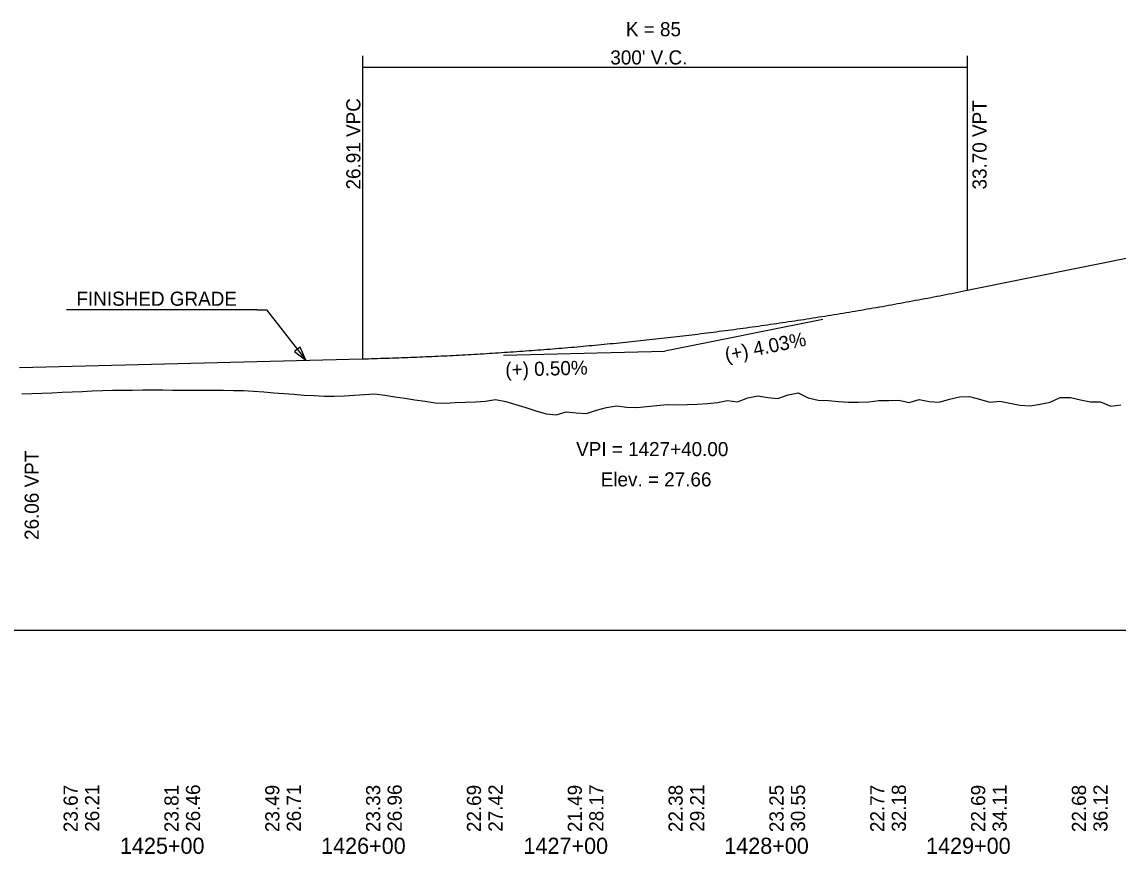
# Model space of a CAD drawing. Extents: x 2360994 to 2383826, y 330623 to 403123.
# Drawn here: x 2370747 to 2371290, y 366762 to 367174 of the extents above; entities that cross this region are included whole.
import ezdxf

# ---------------------------------------------------------------- set-up
doc = ezdxf.new("R2010")
doc.units = 0
for name, color, linetype in [('RD_DDB_GradeTX', 7, 'Continuous'), ('RD_DDB_Profile_EX', 7, 'Continuous'), ('RD_DDB_Profile_Lbl', 7, 'Continuous'), ('RD_DDB_Profile_PR', 7, 'Continuous'), ('RD_DDB_StaTX', 7, 'Continuous'), ('RD_DDB_StripGrade', 7, 'Continuous'), ('RD_DDB_VCLbl', 7, 'Continuous'), ('RD_GPK_Profile_Cell', 7, 'Continuous'), ('RD_TX_Profile', 7, 'Continuous')]:
    doc.layers.add(name, color=color, linetype=linetype)

msp = doc.modelspace()

# ---------------------------------------------------------------- linework, layer by layer
at = {"layer": 'RD_DDB_GradeTX'}
for p in [(2371143.99, 367026.97), (2370985.59, 367009.16)]:
    msp.add_line(p, (2371065.57, 367011.16), dxfattribs=at)
at = {"layer": 'RD_DDB_Profile_EX'}
for points in [[(2370746.72, 366990.04), (2370751.72, 366990.2), (2370756.72, 366990.39), (2370761.72, 366990.62), (2370766.72, 366990.84), (2370771.72, 366991.07), (2370776.72, 366991.3), (2370781.72, 366991.52), (2370786.72, 366991.75), (2370791.72, 366991.82), (2370796.72, 366991.87), (2370801.72, 366991.92), (2370806.72, 366991.97), (2370811.72, 366992.04), (2370816.72, 366992.02), (2370821.72, 366991.91), (2370826.72, 366991.93), (2370831.72, 366991.93), (2370836.72, 366991.91), (2370841.72, 366991.89), (2370846.72, 366991.83), (2370851.72, 366991.76), (2370856.72, 366991.7), (2370861.72, 366991.45), (2370866.72, 366991.04), (2370871.72, 366990.64), (2370876.72, 366990.23), (2370881.72, 366989.82), (2370886.72, 366989.43), (2370891.72, 366989.23), (2370896.72, 366988.95), (2370901.72, 366988.91), (2370906.72, 366989.13), (2370911.72, 366989.45), (2370916.72, 366989.78), (2370921.72, 366990.11), (2370926.72, 366989.38), (2370931.72, 366988.63), (2370936.72, 366987.88), (2370941.72, 366987.13), (2370946.72, 366986.38), (2370951.72, 366985.63), (2370956.72, 366985.45), (2370961.72, 366985.69), (2370966.72, 366985.93), (2370971.72, 366986.17), (2370976.72, 366986.41)], [(2370976.72, 366986.41), (2370981.72, 366987.21), (2370986.72, 366986.27), (2370991.72, 366984.74), (2370996.72, 366983.21), (2371001.72, 366981.68), (2371006.72, 366980.19), (2371011.72, 366979.66), (2371016.72, 366981.18), (2371021.72, 366980.65), (2371026.72, 366980.25), (2371031.72, 366981.95), (2371036.72, 366983.36), (2371041.72, 366984.18), (2371046.72, 366983.51), (2371051.72, 366983.22), (2371056.72, 366983.76), (2371061.72, 366984.3), (2371066.72, 366984.71), (2371071.72, 366984.59), (2371076.72, 366984.82), (2371081.72, 366985.01), (2371086.72, 366985.2), (2371091.72, 366985.81), (2371096.72, 366986.7), (2371101.72, 366986.1), (2371106.72, 366988.07), (2371111.72, 366989.02), (2371116.72, 366988.25), (2371121.72, 366987.8), (2371126.72, 366989.54), (2371131.72, 366990.59), (2371136.72, 366988.09), (2371141.72, 366986.89), (2371146.72, 366986.76), (2371151.72, 366986.25), (2371156.72, 366985.89), (2371161.72, 366985.98), (2371166.72, 366986.17), (2371171.72, 366986.82), (2371176.72, 366986.72), (2371181.72, 366986.86), (2371186.72, 366985.83), (2371191.72, 366987.29), (2371196.72, 366986.27), (2371201.72, 366985.91), (2371206.72, 366987.37), (2371211.72, 366988.65), (2371216.72, 366988.81), (2371221.72, 366987.49), (2371226.72, 366985.97), (2371231.72, 366986.36), (2371236.72, 366985.49), (2371241.72, 366984.47), (2371246.72, 366984.09), (2371251.72, 366984.99), (2371256.72, 366985.93), (2371261.72, 366988.3), (2371266.72, 366988.2), (2371271.72, 366987.05), (2371276.72, 366986.05), (2371281.72, 366986.02), (2371286.72, 366984), (2371291.72, 366984.54)]]:
    msp.add_lwpolyline(points, dxfattribs=at)
at = {"layer": 'RD_DDB_Profile_PR'}
for p, q in [((2371215.47, 367041.38), (2371305.57, 367059.54)), ((2370745.57, 367003.16), (2370915.66, 367007.41))]:
    msp.add_line(p, q, dxfattribs=at)
msp.add_spline([(2370915.66, 367007.41), (2370921.66, 367007.58), (2370927.65, 367007.76), (2370933.65, 367007.96), (2370939.64, 367008.18), (2370945.64, 367008.43), (2370951.64, 367008.7), (2370957.63, 367008.98), (2370963.63, 367009.29), (2370969.63, 367009.62), (2370975.62, 367009.97), (2370981.62, 367010.35), (2370987.61, 367010.74), (2370993.61, 367011.15), (2370999.61, 367011.59), (2371005.6, 367012.05), (2371011.6, 367012.52), (2371017.6, 367013.02), (2371023.59, 367013.54), (2371029.59, 367014.09), (2371035.58, 367014.65), (2371041.58, 367015.23), (2371047.58, 367015.84), (2371053.57, 367016.46), (2371059.57, 367017.11), (2371065.57, 367017.78), (2371071.56, 367018.47), (2371077.56, 367019.18), (2371083.56, 367019.91), (2371089.55, 367020.67), (2371095.55, 367021.44), (2371101.54, 367022.24), (2371107.54, 367023.05), (2371113.54, 367023.89), (2371119.53, 367024.75), (2371125.53, 367025.63), (2371131.53, 367026.53), (2371137.52, 367027.46), (2371143.52, 367028.4), (2371149.51, 367029.37), (2371155.51, 367030.35), (2371161.51, 367031.36), (2371167.5, 367032.39), (2371173.5, 367033.44), (2371179.5, 367034.51), (2371185.49, 367035.6), (2371191.49, 367036.72), (2371197.48, 367037.85), (2371203.48, 367039.01), (2371209.48, 367040.18), (2371215.47, 367041.38)], degree=3, dxfattribs=at)
at = {"layer": 'RD_DDB_VCLbl'}
for p, q in [((2370915.66, 367157.62), (2370915.66, 367007.41)), ((2371215.47, 367157.62), (2371215.47, 367041.38)), ((2370915.66, 367152.1), (2371215.47, 367152.1))]:
    msp.add_line(p, q, dxfattribs=at)
at = {"layer": 'RD_GPK_Profile_Cell'}
msp.add_line((2368825.57, 366872.88), (2372725.57, 366872.88), dxfattribs=at)
at = {"layer": 'RD_TX_Profile'}
msp.add_line((2370863.42, 367031.73), (2370768.86, 367031.73), dxfattribs=at)
msp.add_lwpolyline([(2370863.42, 367031.73), (2370868.07, 367031.73), (2370887.59, 367006.79)], dxfattribs=at)
msp.add_lwpolyline([(2370882, 367011), (2370887.59, 367006.79), (2370884.85, 367013.23)], close=True, dxfattribs=at)

# ---------------------------------------------------------------- texts
at = {"layer": 'RD_DDB_GradeTX'}
for s, rotation, p in [('(+) 4.03%', 11.3972, (2371096.14, 367005.92)), ('(+) 0.50%', 1.4321, (2370986.6, 366998.59))]:
    msp.add_text(s, height=7, rotation=rotation, dxfattribs=at).set_placement(p)
at = {"layer": 'RD_DDB_Profile_Lbl'}
for s, p in [('VPI = 1427+40.00', (2371021.65, 366959.16)), ('Elev. = 27.66', (2371033.84, 366944.16))]:
    msp.add_text(s, height=7, dxfattribs=at).set_placement(p)
at = {"layer": 'RD_DDB_StaTX'}
for s, p in [('1425+00', (2370795.41, 366762)), ('1426+00', (2370895.18, 366762)), ('1427+00', (2370995.54, 366762)), ('1428+00', (2371095.08, 366762)), ('1429+00', (2371195.18, 366762))]:
    msp.add_text(s, height=8, dxfattribs=at).set_placement(p)
at = {"layer": 'RD_DDB_StripGrade'}
for s, p in [('26.91 VPC', (2370914.66, 367091.38)), ('33.70 VPT', (2371225.18, 367091.38)), ('26.06 VPT', (2370755.16, 366917.63)), ('23.67', (2370774.48, 366772.77)), ('26.21', (2370785.15, 366772.95)), ('23.81', (2370824.48, 366772.77)), ('26.46', (2370835.15, 366772.95)), ('23.49', (2370874.48, 366772.77)), ('26.71', (2370885.15, 366772.95)), ('23.33', (2370924.48, 366772.77)), ('26.96', (2370935.15, 366772.95)), ('22.69', (2370974.48, 366772.77)), ('27.42', (2370985.15, 366772.95)), ('21.49', (2371024.48, 366772.77)), ('28.17', (2371035.15, 366772.95)), ('22.38', (2371074.48, 366772.77)), ('29.21', (2371085.15, 366772.95)), ('23.25', (2371124.48, 366772.77)), ('30.55', (2371135.15, 366772.95)), ('22.77', (2371174.48, 366772.77)), ('32.18', (2371185.15, 366772.95)), ('22.69', (2371224.48, 366772.77)), ('34.11', (2371235.15, 366772.95)), ('22.68', (2371274.48, 366772.77)), ('36.12', (2371285.15, 366772.95))]:
    msp.add_text(s, height=7, rotation=90, dxfattribs=at).set_placement(p)
at = {"layer": 'RD_DDB_VCLbl'}
for s, p in [('K = 85', (2371046.3, 367167.35)), ("300' V.C.", (2371038.6, 367153.35))]:
    msp.add_text(s, height=7, dxfattribs=at).set_placement(p)
at = {"layer": 'RD_TX_Profile'}
msp.add_text('FINISHED GRADE', height=7, dxfattribs=at).set_placement((2370773.86, 367033.73))

doc.saveas('drawing.dxf')
